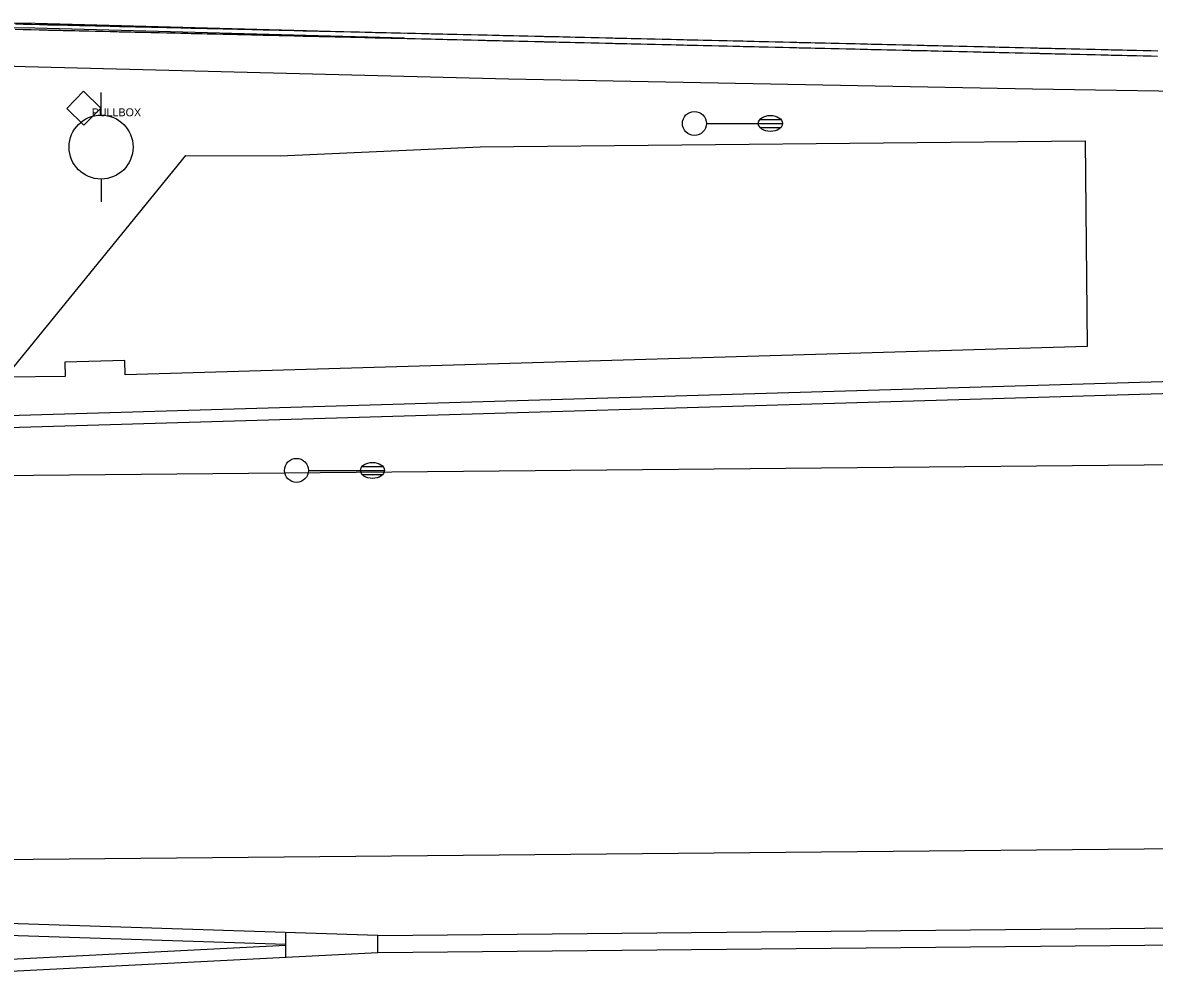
# Model space of a CAD drawing. Extents: x 2145380 to 2157287, y 139568 to 149130.
# Drawn here: x 2147424.2 to 2147565.6, y 143057.5 to 143176.7 of the extents above; entities that cross this region are included whole.
import ezdxf

# ---------------------------------------------------------------- set-up
doc = ezdxf.new("R2010")
doc.units = 0
for name, color, linetype in [('Default', 7, 'Continuous'), ('PR_PREVIOUSLY CONSTRUCTED', 7, 'Continuous'), ('TOPO_Curb Back', 7, 'Continuous'), ('TOPO_Guardrail', 7, 'Continuous'), ('TOPO_Light Pole', 7, 'Continuous'), ('TOPO_Power Pole', 7, 'Continuous'), ('TOPO_Power Pullbox', 7, 'Continuous')]:
    doc.layers.add(name, color=color, linetype=linetype)

# ---------------------------------------------------------------- blocks, each defined once
blk = doc.blocks.new('LP')
at = {"layer": 'TOPO_Light Pole'}
blk.add_line((3.81, 0), (20.32, 0), dxfattribs=at)
for points in [[(20.32, 0), (27.94, 0)], [(20.32, 0), (23.5, 0)], [(20.83, 1.27), (27.43, 1.27)], [(20.83, 1.27), (23.5, 1.27)], [(23.71, 1.27), (27.43, 1.27)], [(23.71, 0), (27.94, 0)], [(20.83, -1.27), (27.43, -1.27)], [(20.83, -1.27), (23.5, -1.27)], [(23.71, -1.27), (27.43, -1.27)]]:
    blk.add_lwpolyline(points, dxfattribs=at)
blk.add_circle((0, 0), 3.81, dxfattribs=at)
blk.add_ellipse((24.13, 0), major_axis=(3.81, 0), ratio=0.666667, dxfattribs=at)
blk = doc.blocks.new('pulbox')
at = {"layer": 'Default'}
blk.add_lwpolyline([(-5.38, -0.01), (-0.02, 5.42), (5.4, 0.06), (0.05, -5.36), (-5.38, -0.01)], dxfattribs=at)
blk.add_text('PULLBOX', height=2.54, dxfattribs=at).set_placement((2.54, -2.54))
blk = doc.blocks.new('POWPOL')
at = {"layer": 'TOPO_Power Pole'}
for p, q in [((0, 10.16), (0, 17.34)), ((0, -10.16), (0, -17.34))]:
    blk.add_line(p, q, dxfattribs=at)
blk.add_circle((0, 0), 10.16, dxfattribs=at)

msp = doc.modelspace()

# ---------------------------------------------------------------- linework, layer by layer
at = {"layer": 'PR_PREVIOUSLY CONSTRUCTED'}
for p, q in [((2146746.76, 143113.71), (2147732.05, 143123.05)), ((2146353.97, 143061.98), (2147732.51, 143075.05)), ((2147468.57, 143062.61), (2147732.6, 143065.11)), ((2147468.57, 143062.61), (2147410.04, 143064.49)), ((2147457.08, 143061.48), (2147410, 143062.99)), ((2147457.09, 143059.9), (2147457.06, 143062.98)), ((2147468.59, 143060.48), (2147468.57, 143062.61)), ((2147468.59, 143060.48), (2147732.62, 143062.99)), ((2147410.03, 143058.99), (2147457.08, 143061.4)), ((2147410.11, 143057.49), (2147468.59, 143060.48))]:
    msp.add_line(p, q, dxfattribs=at)
for points in [[(2147423.27, 143176.59), (2147424.27, 143176.57), (2147425.27, 143176.54), (2147426.27, 143176.52), (2147427.15, 143176.5), (2147427.27, 143176.49), (2147427.41, 143176.49), (2147428.04, 143176.48), (2147428.27, 143176.47), (2147428.92, 143176.46), (2147429.27, 143176.45), (2147429.81, 143176.43), (2147430.27, 143176.42), (2147430.69, 143176.41), (2147431.27, 143176.4), (2147431.58, 143176.39), (2147432.27, 143176.38), (2147432.46, 143176.37), (2147433.27, 143176.35), (2147433.35, 143176.35), (2147434.23, 143176.33), (2147434.27, 143176.33), (2147435.12, 143176.31), (2147435.27, 143176.31), (2147436, 143176.29), (2147436.27, 143176.28), (2147436.89, 143176.27), (2147437.27, 143176.26), (2147437.77, 143176.25), (2147438.27, 143176.24), (2147438.66, 143176.23), (2147439.27, 143176.21), (2147439.54, 143176.21), (2147440.27, 143176.19), (2147440.42, 143176.18), (2147441.27, 143176.16), (2147441.31, 143176.16), (2147442.19, 143176.14), (2147442.26, 143176.14), (2147443.08, 143176.12), (2147443.26, 143176.12), (2147443.96, 143176.1), (2147444.26, 143176.1), (2147444.85, 143176.08), (2147445.26, 143176.07), (2147445.73, 143176.06), (2147446.26, 143176.05), (2147446.62, 143176.04), (2147447.26, 143176.02), (2147447.5, 143176.02), (2147448.26, 143176), (2147448.39, 143176), (2147449.26, 143175.98), (2147449.27, 143175.98), (2147450.16, 143175.96), (2147450.26, 143175.95), (2147451.04, 143175.93), (2147451.26, 143175.93), (2147451.93, 143175.91), (2147452.26, 143175.91), (2147452.81, 143175.89), (2147453.26, 143175.88), (2147453.7, 143175.87), (2147454.26, 143175.86), (2147454.58, 143175.85), (2147455.26, 143175.84), (2147455.46, 143175.83), (2147456.26, 143175.81), (2147456.35, 143175.81), (2147457.23, 143175.79), (2147457.26, 143175.79), (2147458.12, 143175.77), (2147458.26, 143175.77), (2147459, 143175.75), (2147459.26, 143175.74), (2147459.89, 143175.73), (2147460.26, 143175.72), (2147460.77, 143175.71), (2147461.26, 143175.69), (2147461.66, 143175.68), (2147462.26, 143175.67), (2147462.54, 143175.66), (2147463.26, 143175.65), (2147463.43, 143175.64), (2147464.26, 143175.62), (2147464.31, 143175.62), (2147465.2, 143175.6), (2147465.26, 143175.6), (2147466.08, 143175.58), (2147466.26, 143175.58), (2147466.97, 143175.56), (2147467.26, 143175.55), (2147467.85, 143175.54), (2147468.26, 143175.53), (2147468.74, 143175.52), (2147469.26, 143175.51), (2147469.62, 143175.5), (2147470.26, 143175.48), (2147470.5, 143175.48), (2147471.26, 143175.46), (2147471.39, 143175.46), (2147472.26, 143175.43), (2147472.27, 143175.43), (2147473.16, 143175.41), (2147473.26, 143175.41), (2147474.04, 143175.39), (2147474.26, 143175.39), (2147474.93, 143175.37), (2147475.26, 143175.36), (2147475.81, 143175.35), (2147476.26, 143175.34), (2147476.7, 143175.33), (2147477.26, 143175.32), (2147477.58, 143175.31), (2147478.25, 143175.29), (2147478.47, 143175.29), (2147479.25, 143175.27), (2147479.35, 143175.27), (2147480.24, 143175.25), (2147480.25, 143175.25), (2147481.12, 143175.23), (2147481.25, 143175.22), (2147482.01, 143175.21), (2147482.25, 143175.2), (2147482.89, 143175.18), (2147483.25, 143175.18), (2147483.78, 143175.16), (2147484.25, 143175.15), (2147484.66, 143175.14), (2147485.25, 143175.13), (2147485.54, 143175.12), (2147486.25, 143175.1), (2147486.43, 143175.1), (2147487.25, 143175.08), (2147487.31, 143175.08), (2147488.2, 143175.06), (2147488.25, 143175.06), (2147489.08, 143175.04), (2147489.25, 143175.04), (2147489.39, 143175.03), (2147489.97, 143175.02), (2147490.25, 143175.01), (2147490.85, 143175), (2147491.25, 143174.99), (2147491.74, 143174.98), (2147492.25, 143174.96), (2147492.62, 143174.95), (2147493.25, 143174.94), (2147493.51, 143174.93), (2147494.25, 143174.92), (2147494.39, 143174.91), (2147495.25, 143174.89), (2147495.28, 143174.89), (2147496.16, 143174.87), (2147496.25, 143174.87), (2147497.05, 143174.85), (2147497.25, 143174.85), (2147497.93, 143174.83), (2147498.25, 143174.82), (2147498.82, 143174.81), (2147499.25, 143174.8), (2147499.7, 143174.79), (2147500.25, 143174.78), (2147500.59, 143174.77), (2147501.25, 143174.75), (2147501.47, 143174.75), (2147502.25, 143174.73), (2147502.35, 143174.73), (2147503.24, 143174.7), (2147503.25, 143174.7), (2147504.12, 143174.68), (2147504.25, 143174.68), (2147505.01, 143174.66), (2147505.25, 143174.66), (2147505.89, 143174.64), (2147506.25, 143174.63), (2147506.78, 143174.62), (2147507.25, 143174.61), (2147507.66, 143174.6), (2147508.25, 143174.59), (2147508.55, 143174.58), (2147509.25, 143174.56), (2147509.43, 143174.56), (2147510.25, 143174.54), (2147510.32, 143174.54), (2147511.2, 143174.52), (2147511.25, 143174.52), (2147512.09, 143174.5), (2147512.25, 143174.49), (2147512.97, 143174.48), (2147513.25, 143174.47), (2147513.86, 143174.45), (2147514.24, 143174.45), (2147514.74, 143174.43), (2147515.24, 143174.42), (2147515.63, 143174.41), (2147516.24, 143174.4), (2147516.51, 143174.39), (2147517.24, 143174.38), (2147517.4, 143174.37), (2147518.24, 143174.35), (2147518.28, 143174.35), (2147519.16, 143174.33), (2147519.24, 143174.33), (2147520.05, 143174.31), (2147520.08, 143174.31), (2147520.24, 143174.3), (2147520.93, 143174.29), (2147521.24, 143174.28), (2147521.82, 143174.27), (2147522.24, 143174.26), (2147522.7, 143174.25), (2147523.24, 143174.23), (2147523.59, 143174.23), (2147524.24, 143174.21), (2147524.47, 143174.2), (2147525.24, 143174.19), (2147525.36, 143174.18), (2147526.24, 143174.16), (2147527.13, 143174.14), (2147527.24, 143174.14), (2147528.01, 143174.12), (2147528.24, 143174.12), (2147528.9, 143174.1), (2147529.24, 143174.09), (2147529.78, 143174.08), (2147530.24, 143174.07), (2147530.67, 143174.06), (2147531.24, 143174.05), (2147531.55, 143174.04), (2147532.24, 143174.02), (2147532.44, 143174.02), (2147533.24, 143174), (2147533.32, 143174), (2147534.21, 143173.98), (2147534.24, 143173.97), (2147535.09, 143173.95), (2147535.24, 143173.95), (2147535.97, 143173.93), (2147536.24, 143173.93), (2147536.86, 143173.91), (2147537.24, 143173.9), (2147537.74, 143173.89), (2147538.24, 143173.88), (2147538.63, 143173.87), (2147539.24, 143173.86), (2147539.51, 143173.85), (2147539.76, 143173.85), (2147540.24, 143173.83), (2147540.4, 143173.83), (2147541.24, 143173.81), (2147541.28, 143173.81), (2147542.17, 143173.79), (2147542.24, 143173.79), (2147543.05, 143173.77), (2147543.24, 143173.76), (2147543.94, 143173.75), (2147544.24, 143173.74), (2147544.82, 143173.73), (2147545.24, 143173.72), (2147545.71, 143173.7), (2147546.24, 143173.69), (2147546.59, 143173.68), (2147547.24, 143173.67), (2147547.47, 143173.66), (2147548.24, 143173.64), (2147548.36, 143173.64), (2147549.24, 143173.62), (2147549.24, 143173.62), (2147550.13, 143173.6), (2147550.23, 143173.6), (2147551.01, 143173.58), (2147551.23, 143173.57), (2147551.38, 143173.57), (2147551.9, 143173.56), (2147552.23, 143173.55), (2147552.78, 143173.54), (2147553.23, 143173.53), (2147553.67, 143173.52), (2147554.23, 143173.5), (2147554.55, 143173.5), (2147555.23, 143173.48), (2147555.44, 143173.48), (2147556.23, 143173.46), (2147556.32, 143173.45), (2147557.21, 143173.43), (2147557.23, 143173.43), (2147558.09, 143173.41), (2147558.23, 143173.41), (2147558.98, 143173.39), (2147559.23, 143173.39), (2147559.86, 143173.37), (2147560.23, 143173.36), (2147560.75, 143173.35), (2147561.23, 143173.34), (2147561.63, 143173.33), (2147562.23, 143173.32), (2147562.51, 143173.31), (2147563.23, 143173.29), (2147563.4, 143173.29), (2147564.23, 143173.27), (2147564.28, 143173.27), (2147565.17, 143173.25), (2147565.23, 143173.24), (2147566.05, 143173.23)], [(2147423.25, 143175.92), (2147424.25, 143175.9), (2147425.25, 143175.88), (2147426.25, 143175.85), (2147427.14, 143175.83), (2147427.25, 143175.83), (2147427.39, 143175.82), (2147428.02, 143175.81), (2147428.25, 143175.8), (2147428.91, 143175.79), (2147429.25, 143175.78), (2147429.79, 143175.77), (2147430.25, 143175.76), (2147430.68, 143175.75), (2147431.25, 143175.73), (2147431.56, 143175.73), (2147432.25, 143175.71), (2147432.45, 143175.7), (2147433.25, 143175.69), (2147433.33, 143175.68), (2147434.22, 143175.66), (2147434.25, 143175.66), (2147435.1, 143175.64), (2147435.25, 143175.64), (2147435.99, 143175.62), (2147436.25, 143175.61), (2147436.87, 143175.6), (2147437.25, 143175.59), (2147437.75, 143175.58), (2147438.25, 143175.57), (2147438.64, 143175.56), (2147439.25, 143175.55), (2147439.52, 143175.54), (2147440.25, 143175.52), (2147440.41, 143175.52), (2147441.25, 143175.5), (2147441.29, 143175.5), (2147442.18, 143175.48), (2147442.25, 143175.47), (2147443.06, 143175.45), (2147443.25, 143175.45), (2147443.95, 143175.43), (2147444.25, 143175.43), (2147444.83, 143175.41), (2147445.25, 143175.4), (2147445.72, 143175.39), (2147446.25, 143175.38), (2147446.6, 143175.37), (2147447.25, 143175.36), (2147447.49, 143175.35), (2147448.25, 143175.33), (2147448.37, 143175.33), (2147449.25, 143175.31), (2147449.26, 143175.31), (2147450.14, 143175.29), (2147450.25, 143175.29), (2147451.03, 143175.27), (2147451.25, 143175.26), (2147451.91, 143175.25), (2147452.25, 143175.24), (2147452.79, 143175.23), (2147453.25, 143175.21), (2147453.68, 143175.2), (2147454.25, 143175.19), (2147454.56, 143175.18), (2147455.25, 143175.17), (2147455.45, 143175.16), (2147456.25, 143175.14), (2147456.33, 143175.14), (2147457.22, 143175.12), (2147457.25, 143175.12), (2147458.1, 143175.1), (2147458.24, 143175.1), (2147458.99, 143175.08), (2147459.24, 143175.07), (2147459.87, 143175.06), (2147460.24, 143175.05), (2147460.76, 143175.04), (2147461.24, 143175.03), (2147461.64, 143175.02), (2147462.24, 143175), (2147462.53, 143175), (2147463.24, 143174.98), (2147463.41, 143174.98), (2147464.24, 143174.96), (2147464.3, 143174.95), (2147465.18, 143174.93), (2147465.24, 143174.93), (2147466.07, 143174.91), (2147466.24, 143174.91), (2147466.95, 143174.89), (2147467.24, 143174.88), (2147467.84, 143174.87), (2147468.24, 143174.86), (2147468.72, 143174.85), (2147469.24, 143174.84), (2147469.6, 143174.83), (2147470.24, 143174.82), (2147470.49, 143174.81), (2147471.24, 143174.79), (2147471.37, 143174.79), (2147472.24, 143174.77), (2147472.26, 143174.77), (2147473.14, 143174.75), (2147473.24, 143174.74), (2147474.03, 143174.73), (2147474.24, 143174.72), (2147474.91, 143174.7), (2147475.24, 143174.7), (2147475.8, 143174.68), (2147476.24, 143174.67), (2147476.68, 143174.66), (2147477.24, 143174.65), (2147477.57, 143174.64), (2147478.24, 143174.63), (2147478.45, 143174.62), (2147479.24, 143174.6), (2147479.34, 143174.6), (2147480.22, 143174.58), (2147480.24, 143174.58), (2147481.11, 143174.56), (2147481.24, 143174.56), (2147481.99, 143174.54), (2147482.24, 143174.53), (2147482.88, 143174.52), (2147483.24, 143174.51), (2147483.76, 143174.5), (2147484.24, 143174.48), (2147484.65, 143174.47), (2147485.24, 143174.46), (2147485.53, 143174.45), (2147486.24, 143174.44), (2147486.41, 143174.43), (2147487.24, 143174.41), (2147487.3, 143174.41), (2147488.18, 143174.39), (2147488.24, 143174.39), (2147489.07, 143174.37), (2147489.24, 143174.37), (2147489.38, 143174.36), (2147489.95, 143174.35), (2147490.24, 143174.34), (2147490.84, 143174.33), (2147491.24, 143174.32), (2147491.72, 143174.31), (2147492.24, 143174.3), (2147492.61, 143174.29), (2147493.24, 143174.27), (2147493.49, 143174.27), (2147494.23, 143174.25), (2147494.38, 143174.25), (2147495.23, 143174.23), (2147495.26, 143174.22), (2147496.15, 143174.2), (2147496.23, 143174.2), (2147497.03, 143174.18), (2147497.23, 143174.18), (2147497.92, 143174.16), (2147498.23, 143174.15), (2147498.8, 143174.14), (2147499.23, 143174.13), (2147499.69, 143174.12), (2147500.23, 143174.11), (2147500.57, 143174.1), (2147501.23, 143174.08), (2147501.46, 143174.08), (2147502.23, 143174.06), (2147502.34, 143174.06), (2147503.22, 143174.04), (2147503.23, 143174.04), (2147504.11, 143174.02), (2147504.23, 143174.01), (2147504.99, 143174), (2147505.23, 143173.99), (2147505.88, 143173.97), (2147506.23, 143173.97), (2147506.76, 143173.95), (2147507.23, 143173.94), (2147507.65, 143173.93), (2147508.23, 143173.92), (2147508.53, 143173.91), (2147509.23, 143173.9), (2147509.42, 143173.89), (2147510.23, 143173.87), (2147510.3, 143173.87), (2147511.19, 143173.85), (2147511.23, 143173.85), (2147512.07, 143173.83), (2147512.23, 143173.83), (2147512.96, 143173.81), (2147513.23, 143173.8), (2147513.84, 143173.79), (2147514.23, 143173.78), (2147514.72, 143173.77), (2147515.23, 143173.76), (2147515.61, 143173.75), (2147516.23, 143173.73), (2147516.49, 143173.72), (2147517.23, 143173.71), (2147517.38, 143173.7), (2147518.23, 143173.68), (2147518.26, 143173.68), (2147519.15, 143173.66), (2147519.23, 143173.66), (2147520.03, 143173.64), (2147520.07, 143173.64), (2147520.23, 143173.64), (2147520.92, 143173.62), (2147521.23, 143173.61), (2147521.8, 143173.6), (2147522.23, 143173.59), (2147522.69, 143173.58), (2147523.23, 143173.57), (2147523.57, 143173.56), (2147524.23, 143173.54), (2147524.46, 143173.54), (2147525.23, 143173.52), (2147525.34, 143173.52), (2147526.23, 143173.5), (2147527.11, 143173.47), (2147527.23, 143173.47), (2147528, 143173.45), (2147528.23, 143173.45), (2147528.88, 143173.43), (2147529.23, 143173.42), (2147529.76, 143173.41), (2147530.22, 143173.4), (2147530.65, 143173.39), (2147531.22, 143173.38), (2147531.53, 143173.37), (2147532.22, 143173.35), (2147532.42, 143173.35), (2147533.22, 143173.33), (2147533.3, 143173.33), (2147534.19, 143173.31), (2147534.22, 143173.31), (2147535.07, 143173.29), (2147535.22, 143173.28), (2147535.96, 143173.27), (2147536.22, 143173.26), (2147536.84, 143173.25), (2147537.22, 143173.24), (2147537.73, 143173.22), (2147538.22, 143173.21), (2147538.61, 143173.2), (2147539.22, 143173.19), (2147539.5, 143173.18), (2147539.74, 143173.18), (2147540.22, 143173.17), (2147540.38, 143173.16), (2147541.22, 143173.14), (2147541.27, 143173.14), (2147542.15, 143173.12), (2147542.22, 143173.12), (2147543.04, 143173.1), (2147543.22, 143173.1), (2147543.92, 143173.08), (2147544.22, 143173.07), (2147544.8, 143173.06), (2147545.22, 143173.05), (2147545.69, 143173.04), (2147546.22, 143173.02), (2147546.57, 143173.02), (2147547.22, 143173), (2147547.46, 143173), (2147548.22, 143172.98), (2147548.34, 143172.97), (2147549.22, 143172.95), (2147549.23, 143172.95), (2147550.11, 143172.93), (2147550.22, 143172.93), (2147551, 143172.91), (2147551.22, 143172.91), (2147551.36, 143172.9), (2147551.88, 143172.89), (2147552.22, 143172.88), (2147552.77, 143172.87), (2147553.22, 143172.86), (2147553.65, 143172.85), (2147554.22, 143172.84), (2147554.54, 143172.83), (2147555.22, 143172.81), (2147555.42, 143172.81), (2147556.22, 143172.79), (2147556.31, 143172.79), (2147557.19, 143172.77), (2147557.22, 143172.77), (2147558.08, 143172.75), (2147558.22, 143172.74), (2147558.96, 143172.72), (2147559.22, 143172.72), (2147559.85, 143172.7), (2147560.22, 143172.69), (2147560.73, 143172.68), (2147561.22, 143172.67), (2147561.62, 143172.66), (2147562.22, 143172.65), (2147562.5, 143172.64), (2147563.22, 143172.62), (2147563.38, 143172.62), (2147564.22, 143172.6), (2147564.27, 143172.6), (2147565.15, 143172.58), (2147565.22, 143172.58), (2147566.04, 143172.56)], [(2146746.61, 143129.21), (2147125.89, 143132.8), (2147166.18, 143125.18), (2147422.32, 143127.61), (2147722.25, 143136.46), (2147731.92, 143136.55)], [(2146746.63, 143127.71), (2147125.75, 143131.3), (2147166.04, 143123.68), (2147422.35, 143126.11), (2147722.28, 143134.96), (2147731.94, 143135.05)]]:
    msp.add_lwpolyline(points, dxfattribs=at)
msp.add_lwpolyline([(2147427.12, 143138.67), (2147444.59, 143160.15), (2147456.38, 143160.08), (2147481.36, 143161.2), (2147557, 143161.96), (2147557.25, 143136.26), (2147436.99, 143132.71), (2147436.94, 143134.51), (2147429.45, 143134.28), (2147429.51, 143132.49), (2147422.05, 143132.42)], close=True, dxfattribs=at)
at = {"layer": 'TOPO_Curb Back'}
for points in [[(2147471.91, 143175.39), (2147425.73, 143176.64), (2147406.14, 143176.75)], [(2147471.89, 143174.79), (2147425.72, 143176.04), (2147406.14, 143176.15)]]:
    msp.add_lwpolyline(points, dxfattribs=at)
at = {"layer": 'TOPO_Guardrail'}
msp.add_lwpolyline([(2147396.72, 143169.74), (2147407.41, 143171.81), (2147424.51, 143171.24), (2147484.91, 143169.71), (2147550.4, 143168.46), (2147576.68, 143168.04)], dxfattribs=at)

# ---------------------------------------------------------------- block references
at = {"layer": 'TOPO_Light Pole', "xscale": 0.39370000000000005, "yscale": 0.3937000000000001}
for p in [(2147508.14, 143164.14), (2147458.4, 143120.76)]:
    msp.add_blockref('LP', p, dxfattribs=at)
at = {"layer": 'TOPO_Power Pole', "xscale": 0.39370000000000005, "yscale": 0.3937000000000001}
msp.add_blockref('POWPOL', (2147433.98, 143161.18), dxfattribs=at)
at = {"layer": 'TOPO_Power Pullbox', "xscale": 0.39370000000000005, "yscale": 0.3937000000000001}
msp.add_blockref('pulbox', (2147431.81, 143166.03), dxfattribs=at)

doc.saveas('drawing.dxf')
